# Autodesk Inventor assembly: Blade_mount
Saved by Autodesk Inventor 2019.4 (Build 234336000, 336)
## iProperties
Created: 2020-02
Part Number: Blade_mount
Document SubType Name: Assembly
Designer: Administrator
Title: Blade_mount v18
Author: Administrator
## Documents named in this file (10)
- c:\worker\convert-fusion-r01\tmp\job-1\5\output\files\e4333473-a38b-4431-9958-ad24a2f67704\Blade_mount v18_2.iam
- c:\worker\convert-fusion-r01\tmp\job-1\5\output\files\e4333473-a38b-4431-9958-ad24a2f67704\Component1.ipt
- c:\worker\convert-fusion-r01\tmp\job-1\5\output\files\e4333473-a38b-4431-9958-ad24a2f67704\Component2.ipt
- c:\worker\convert-fusion-r01\tmp\job-1\5\output\files\e4333473-a38b-4431-9958-ad24a2f67704\Component3.ipt
- c:\worker\convert-fusion-r01\tmp\job-1\5\output\files\e4333473-a38b-4431-9958-ad24a2f67704\Component4.ipt
- c:\worker\convert-fusion-r01\tmp\job-1\5\output\files\e4333473-a38b-4431-9958-ad24a2f67704\Component5.ipt
- c:\worker\convert-fusion-r01\tmp\job-1\5\output\files\e4333473-a38b-4431-9958-ad24a2f67704\Component6.ipt
- c:\worker\convert-fusion-r01\tmp\job-1\5\output\files\e4333473-a38b-4431-9958-ad24a2f67704\Component7.ipt
- c:\worker\convert-fusion-r01\tmp\job-1\5\output\files\e4333473-a38b-4431-9958-ad24a2f67704\Component8.ipt
- c:\worker\convert-fusion-r01\tmp\job-1\5\output\files\e4333473-a38b-4431-9958-ad24a2f67704\Component9.ipt
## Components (9 placed, 9 different names)
1. Component1:1
2. Component2:1
3. Component3:1
4. Component4:1
5. Component5:1
6. Component6:1
7. Component7:1
8. Component8:1
9. Component9:1
